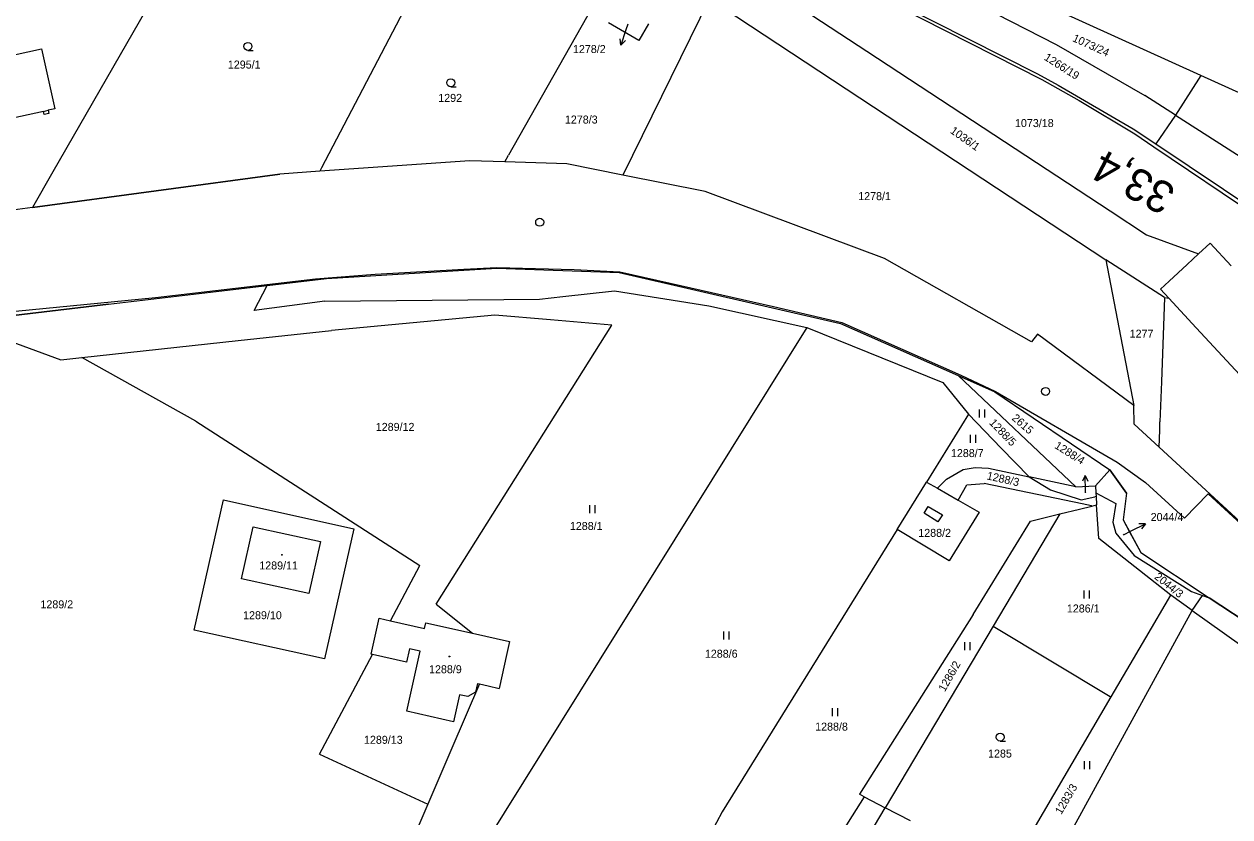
# Model space of a CAD drawing. Extents: x -805011 to -803920, y -1150790 to -1150234.
# Drawn here: x -804429.5 to -804203.4, y -1150584.2 to -1150435.6 of the extents above; entities that cross this region are included whole.
import ezdxf

# ---------------------------------------------------------------- set-up
doc = ezdxf.new("R2010")
doc.units = 0
for name, color, linetype in [('Default', 7, 'Continuous'), ('kilometráž - vrstava 7', 7, 'Continuous'), ('kn_celek - Cisla parcel pomocna', 7, 'Continuous'), ('kn_celek - Cisla pozemkovych parcel', 7, 'Continuous'), ('kn_celek - Cisla stavebnich parcel', 7, 'Continuous'), ('kn_celek - Hranice parcel', 7, 'Continuous'), ('kn_celek - Vnitrni kresby', 7, 'Continuous'), ('kn_celek - Znacky budov', 7, 'Continuous'), ('kn_celek - Znacky kultur', 7, 'Continuous'), ('plochy - SZDC', 7, 'Continuous'), ('PSR_C2_2_trasa_Vimperk - Kabelová trasa', 7, 'Continuous')]:
    doc.layers.add(name, color=color, linetype=linetype)

# ---------------------------------------------------------------- blocks, each defined once
blk = doc.blocks.new('306')
at = {"layer": 'Default'}
for p, q in [((-5.2, 0), (-5.2, 15)), ((4.8, 0), (4.8, 15))]:
    blk.add_line(p, q, dxfattribs=at)
blk = doc.blocks.new('304')
at = {"layer": 'Default'}
blk.add_line((-0.1, 0), (9.9, 0), dxfattribs=at)
blk.add_circle((-0.1, 7.5), 7.5, dxfattribs=at)
blk = doc.blocks.new('402')
at = {"layer": 'Default'}
for p, q in [((-0.8, 0.8), (0.7, 0.8)), ((-0.8, 0.8), (-0.8, -0.7)), ((0.7, 0.8), (0.7, -0.7)), ((0.7, -0.7), (-0.8, -0.7))]:
    blk.add_line(p, q, dxfattribs=at)
blk = doc.blocks.new('Z61')
at = {"layer": 'Default'}
for p, q in [((0, 0), (30, 0)), ((30, 0), (19.2, 5.3)), ((30, 0), (19.2, -5.3))]:
    blk.add_line(p, q, dxfattribs=at)

msp = doc.modelspace()

# ---------------------------------------------------------------- linework, layer by layer
at = {"layer": 'kilometráž - vrstava 7'}
for centre in [(-804332.82, -1150472.71), (-804237.98, -1150504.43)]:
    msp.add_circle(centre, 0.75, dxfattribs=at)
at = {"layer": 'kn_celek - Cisla parcel pomocna'}
for p, q in [((-804316.32, -1150435.58), (-804316.66, -1150436.63)), ((-804230.51, -1150523.46), (-804230.52, -1150523.18)), ((-804223.38, -1150531.32), (-804221.96, -1150530.6))]:
    msp.add_line(p, q, dxfattribs=at)
at = {"layer": 'kn_celek - Hranice parcel'}
for p, q in [((-804385.7, -1150396.46), (-804424.05, -1150463.28)), ((-804298.67, -1150422.8), (-804271.5, -1150440.64)), ((-804208.87, -1150445.2), (-804247.42, -1150427.68)), ((-804321.6, -1150429.95), (-804338.65, -1150460.11)), ((-804357.62, -1150431.72), (-804373.69, -1150462.54)), ((-804301, -1150430.74), (-804317.22, -1150463.88)), ((-804301, -1150430.74), (-804226.72, -1150479.76)), ((-804265.66, -1150432.25), (-804238.71, -1150445.94)), ((-804265.36, -1150431.82), (-804239.5, -1150444.89)), ((-804250.04, -1150432.2), (-804236.02, -1150439.39)), ((-804314.22, -1150438.61), (-804319.91, -1150435.33)), ((-804312.41, -1150435.5), (-804314.22, -1150438.61)), ((-804236.02, -1150439.39), (-804219.37, -1150448.94)), ((-804498.86, -1150456.4), (-804426.19, -1150440.19)), ((-804426.19, -1150440.19), (-804423.68, -1150451.44)), ((-804271.5, -1150440.64), (-804225.88, -1150470.58)), ((-804239.5, -1150444.89), (-804235.62, -1150446.99)), ((-804238.71, -1150445.94), (-804231.71, -1150449.89)), ((-804208.87, -1150445.2), (-804213.63, -1150452.62)), ((-804163.83, -1150465.67), (-804208.87, -1150445.2)), ((-804235.62, -1150446.99), (-804221.57, -1150455.2)), ((-804231.71, -1150449.89), (-804221.27, -1150456.12)), ((-804213.63, -1150452.62), (-804219.37, -1150448.94)), ((-804425.85, -1150451.92), (-804476.67, -1150463.25)), ((-804425.72, -1150452.51), (-804425.85, -1150451.92)), ((-804424.84, -1150452.31), (-804425.72, -1150452.51)), ((-804423.68, -1150451.44), (-804424.97, -1150451.73)), ((-804424.97, -1150451.73), (-804424.84, -1150452.31)), ((-804213.63, -1150452.62), (-804217.33, -1150458.04)), ((-804213.63, -1150452.62), (-804176.02, -1150476.77)), ((-804221.57, -1150455.2), (-804217.33, -1150458.04)), ((-804221.27, -1150456.12), (-804217.68, -1150458.55)), ((-804217.68, -1150458.55), (-804183.31, -1150481.83)), ((-804217.33, -1150458.04), (-804188.61, -1150477.27)), ((-804345.91, -1150461.18), (-804374.01, -1150463.14)), ((-804339.38, -1150461.4), (-804345.91, -1150461.18)), ((-804339.38, -1150461.4), (-804338.65, -1150460.11)), ((-804327.71, -1150461.78), (-804339.38, -1150461.4)), ((-804317.22, -1150463.88), (-804327.71, -1150461.78)), ((-804424.05, -1150463.28), (-804427.86, -1150469.92)), ((-804427.86, -1150469.92), (-804381.52, -1150463.67)), ((-804374.01, -1150463.14), (-804381.52, -1150463.67)), ((-804373.69, -1150462.54), (-804374.01, -1150463.14)), ((-804301.77, -1150466.98), (-804317.22, -1150463.88)), ((-804268.19, -1150479.5), (-804301.77, -1150466.98)), ((-804427.86, -1150469.92), (-804473.24, -1150476.04)), ((-804225.88, -1150470.58), (-804219.07, -1150475.05)), ((-804219.07, -1150475.05), (-804209.3, -1150478.65)), ((-804207.15, -1150476.64), (-804209.3, -1150478.65)), ((-804207.15, -1150476.64), (-804203.22, -1150480.89)), ((-804240.65, -1150495.11), (-804268.19, -1150479.5)), ((-804215.71, -1150486.85), (-804226.72, -1150479.76)), ((-804226.72, -1150479.76), (-804221.47, -1150507.06)), ((-804209.3, -1150478.65), (-804211.42, -1150480.62)), ((-804372.75, -1150483.24), (-804340.86, -1150481.33)), ((-804340.86, -1150481.33), (-804317.89, -1150482.17)), ((-804317.89, -1150482.17), (-804276.4, -1150491.69)), ((-804211.42, -1150480.62), (-804214.82, -1150483.78)), ((-804413.66, -1150488.07), (-804383.87, -1150484.55)), ((-804386.34, -1150489.27), (-804383.87, -1150484.55)), ((-804383.87, -1150484.55), (-804372.75, -1150483.24)), ((-804214.82, -1150483.78), (-804216.44, -1150485.29)), ((-804332.85, -1150487.17), (-804328.48, -1150486.67)), ((-804328.48, -1150486.67), (-804318.77, -1150485.56)), ((-804318.77, -1150485.56), (-804301.09, -1150488.42)), ((-804216.44, -1150485.29), (-804214.9, -1150486.96)), ((-804215.71, -1150486.85), (-804216.27, -1150502.62)), ((-804215.71, -1150486.85), (-804214.9, -1150486.96)), ((-804214.9, -1150486.96), (-804209.74, -1150492.54)), ((-804413.66, -1150488.07), (-804432.51, -1150490.32)), ((-804373.12, -1150487.5), (-804386.34, -1150489.27)), ((-804373.12, -1150487.5), (-804332.85, -1150487.17)), ((-804301.09, -1150488.42), (-804282.73, -1150492.43)), ((-804341.25, -1150490.12), (-804371.82, -1150493.04)), ((-804330.8, -1150491.03), (-804341.25, -1150490.12)), ((-804319.3, -1150492.03), (-804330.8, -1150491.03)), ((-804436.85, -1150493.24), (-804422.59, -1150498.49)), ((-804389.32, -1150494.92), (-804371.82, -1150493.04)), ((-804352.2, -1150544.3), (-804319.3, -1150492.03)), ((-804282.73, -1150492.43), (-804344.13, -1150590.85)), ((-804282.73, -1150492.43), (-804257.22, -1150502.78)), ((-804276.4, -1150491.69), (-804254.35, -1150501.48)), ((-804239.52, -1150493.68), (-804240.65, -1150495.11)), ((-804221.47, -1150507.06), (-804239.52, -1150493.68)), ((-804209.74, -1150492.54), (-804206.45, -1150496.09)), ((-804418.66, -1150498.07), (-804389.32, -1150494.92)), ((-804422.59, -1150498.49), (-804418.66, -1150498.07)), ((-804397.29, -1150510.02), (-804418.66, -1150498.07)), ((-804206.45, -1150496.09), (-804175.77, -1150529.26)), ((-804257.22, -1150502.78), (-804252.42, -1150508.72)), ((-804254.35, -1150501.48), (-804247.48, -1150504.53)), ((-804232.31, -1150522.31), (-804254.35, -1150501.48)), ((-804216.27, -1150502.62), (-804216.54, -1150510.11)), ((-804247.48, -1150504.53), (-804225.97, -1150519.11)), ((-804221.41, -1150510.55), (-804221.47, -1150507.06)), ((-804252.42, -1150508.72), (-804260.3, -1150521.44)), ((-804252.42, -1150508.72), (-804246.34, -1150515.05)), ((-804397.29, -1150510.02), (-804355.28, -1150537.09)), ((-804221.41, -1150510.55), (-804216.71, -1150514.88)), ((-804216.71, -1150514.88), (-804216.6, -1150511.73)), ((-804216.6, -1150511.73), (-804216.54, -1150510.11)), ((-804241.05, -1150520.43), (-804246.34, -1150515.05)), ((-804216.71, -1150514.88), (-804196.65, -1150533.37)), ((-804258.26, -1150522.6), (-804256.57, -1150520.87)), ((-804256.57, -1150520.87), (-804253.42, -1150519.06)), ((-804253.42, -1150519.06), (-804251.17, -1150518.68)), ((-804251.17, -1150518.68), (-804248.68, -1150518.8)), ((-804248.68, -1150518.8), (-804241.05, -1150520.43)), ((-804241.05, -1150520.43), (-804237.05, -1150522.86)), ((-804232.31, -1150522.31), (-804241.05, -1150520.43)), ((-804228.6, -1150522.11), (-804225.97, -1150519.11)), ((-804222.81, -1150523.51), (-804225.97, -1150519.11)), ((-804265.8, -1150530.32), (-804260.3, -1150521.44)), ((-804260.3, -1150521.44), (-804258.26, -1150522.6)), ((-804258.26, -1150522.6), (-804254.38, -1150524.81)), ((-804254.38, -1150524.81), (-804252.74, -1150521.97)), ((-804252.74, -1150521.97), (-804249.49, -1150521.69)), ((-804231.13, -1150525.52), (-804249.49, -1150521.69)), ((-804237.05, -1150522.86), (-804231.31, -1150524.77)), ((-804232.31, -1150522.31), (-804228.6, -1150522.11)), ((-804228.6, -1150522.11), (-804228.54, -1150523.48)), ((-804397.61, -1150549.18), (-804392.08, -1150524.79)), ((-804392.08, -1150524.79), (-804367.66, -1150530.19)), ((-804254.38, -1150524.81), (-804250.43, -1150527.06)), ((-804231.31, -1150524.77), (-804228.73, -1150524.18)), ((-804228.51, -1150524.13), (-804228.73, -1150524.18)), ((-804228.54, -1150523.48), (-804228.51, -1150524.13)), ((-804228.54, -1150523.48), (-804224.81, -1150525.46)), ((-804228.51, -1150524.13), (-804228.45, -1150525.73)), ((-804222.81, -1150523.51), (-804223.47, -1150528.51)), ((-804250.43, -1150527.06), (-804256.08, -1150536.2)), ((-804235.33, -1150527.4), (-804247.84, -1150548.47)), ((-804240.82, -1150528.74), (-804235.33, -1150527.4)), ((-804235.33, -1150527.4), (-804231.62, -1150526.5)), ((-804231.62, -1150526.5), (-804229.32, -1150525.94)), ((-804229.39, -1150525.88), (-804231.13, -1150525.52)), ((-804229.39, -1150525.88), (-804229.32, -1150525.94)), ((-804229.32, -1150525.94), (-804228.45, -1150525.73)), ((-804228.03, -1150531.99), (-804228.45, -1150525.73)), ((-804224.81, -1150525.46), (-804225.36, -1150528.93)), ((-804388.69, -1150539.57), (-804386.51, -1150529.81)), ((-804386.51, -1150529.81), (-804373.89, -1150532.57)), ((-804251.57, -1150546.24), (-804240.82, -1150528.74)), ((-804225.36, -1150528.93), (-804224.83, -1150531.01)), ((-804223.47, -1150528.51), (-804220.13, -1150534.61)), ((-804367.66, -1150530.19), (-804373.16, -1150554.57)), ((-804265.8, -1150530.32), (-804298.61, -1150583.27)), ((-804256.08, -1150536.2), (-804265.8, -1150530.32)), ((-804214.51, -1150542.63), (-804228.03, -1150531.99)), ((-804224.83, -1150531.01), (-804221.38, -1150535.19)), ((-804373.89, -1150532.57), (-804376.12, -1150542.34)), ((-804221.38, -1150535.19), (-804210.61, -1150541.96)), ((-804220.13, -1150534.61), (-804207.3, -1150543.14)), ((-804360.79, -1150547.46), (-804355.28, -1150537.09)), ((-804376.12, -1150542.34), (-804388.69, -1150539.57)), ((-804219.19, -1150550.65), (-804214.51, -1150542.63)), ((-804210.52, -1150545.49), (-804214.51, -1150542.63)), ((-804210.61, -1150541.96), (-804208.56, -1150542.69)), ((-804210.52, -1150545.49), (-804208.56, -1150542.69)), ((-804208.56, -1150542.69), (-804207.3, -1150543.14)), ((-804196.79, -1150550.13), (-804207.3, -1150543.14)), ((-804352.2, -1150544.3), (-804345.42, -1150549.78)), ((-804237.26, -1150594.36), (-804210.52, -1150545.49)), ((-804210.52, -1150545.49), (-804197.78, -1150554.62)), ((-804364.41, -1150553.72), (-804362.93, -1150546.98)), ((-804362.93, -1150546.98), (-804360.79, -1150547.46)), ((-804360.79, -1150547.46), (-804354.4, -1150548.88)), ((-804354.4, -1150548.88), (-804354.17, -1150547.83)), ((-804354.17, -1150547.83), (-804345.42, -1150549.78)), ((-804251.57, -1150546.24), (-804272.88, -1150579.95)), ((-804373.16, -1150554.57), (-804397.61, -1150549.18)), ((-804345.42, -1150549.78), (-804338.45, -1150551.33)), ((-804247.84, -1150548.47), (-804268.04, -1150582.49)), ((-804247.84, -1150548.47), (-804225.88, -1150561.63)), ((-804338.45, -1150551.33), (-804338.96, -1150553.59)), ((-804225.71, -1150561.73), (-804219.19, -1150550.65)), ((-804374.09, -1150572.48), (-804364.15, -1150553.78)), ((-804364.15, -1150553.78), (-804364.41, -1150553.72)), ((-804357.78, -1150555.19), (-804364.15, -1150553.78)), ((-804357.21, -1150552.7), (-804357.78, -1150555.19)), ((-804357.73, -1150564.42), (-804355.25, -1150553.13)), ((-804355.25, -1150553.13), (-804357.21, -1150552.7)), ((-804338.96, -1150553.59), (-804340.43, -1150560.12)), ((-804344.07, -1150559.29), (-804349.26, -1150571.32)), ((-804344.48, -1150559.2), (-804344.87, -1150560.8)), ((-804344.48, -1150559.2), (-804344.07, -1150559.29)), ((-804344.07, -1150559.29), (-804342.48, -1150559.65)), ((-804347.82, -1150561.33), (-804348.99, -1150566.39)), ((-804346.3, -1150561.65), (-804347.82, -1150561.33)), ((-804344.87, -1150560.8), (-804346.3, -1150561.65)), ((-804342.48, -1150559.65), (-804340.43, -1150560.12)), ((-804244.16, -1150593.22), (-804225.71, -1150561.73)), ((-804225.88, -1150561.63), (-804225.71, -1150561.73)), ((-804348.99, -1150566.39), (-804357.73, -1150564.42)), ((-804374.09, -1150572.48), (-804353.79, -1150581.83)), ((-804349.26, -1150571.32), (-804353.79, -1150581.83)), ((-804353.79, -1150581.83), (-804355.87, -1150586.66)), ((-804271.97, -1150580.46), (-804281.49, -1150595.48)), ((-804271.97, -1150580.46), (-804272.88, -1150579.95)), ((-804271.97, -1150580.46), (-804268.04, -1150582.49)), ((-804298.61, -1150583.27), (-804317.72, -1150619.16)), ((-804272.21, -1150589.52), (-804268.04, -1150582.49)), ((-804263.3, -1150584.93), (-804268.04, -1150582.49))]:
    msp.add_line(p, q, dxfattribs=at)
at = {"layer": 'kn_celek - Vnitrni kresby'}
for p, q in [((-804425.85, -1150451.92), (-804424.97, -1150451.73)), ((-804260.76, -1150527.29), (-804259.98, -1150526.02)), ((-804258.17, -1150528.89), (-804260.76, -1150527.29)), ((-804259.98, -1150526.02), (-804257.34, -1150527.57)), ((-804257.34, -1150527.57), (-804258.17, -1150528.89))]:
    msp.add_line(p, q, dxfattribs=at)
at = {"layer": 'plochy - SZDC'}
for p, q in [((-804345.91, -1150461.18), (-804374.01, -1150463.14)), ((-804339.38, -1150461.4), (-804345.91, -1150461.18)), ((-804327.71, -1150461.78), (-804339.38, -1150461.4)), ((-804317.22, -1150463.88), (-804327.71, -1150461.78)), ((-804381.52, -1150463.67), (-804427.86, -1150469.92)), ((-804374.01, -1150463.14), (-804381.52, -1150463.67)), ((-804301.77, -1150466.98), (-804317.22, -1150463.88)), ((-804268.19, -1150479.5), (-804301.77, -1150466.98)), ((-804427.86, -1150469.92), (-804473.24, -1150476.04)), ((-804240.65, -1150495.11), (-804268.19, -1150479.5)), ((-804372.75, -1150483.24), (-804340.86, -1150481.33)), ((-804340.86, -1150481.33), (-804317.89, -1150482.17)), ((-804317.89, -1150482.17), (-804276.4, -1150491.69)), ((-804413.66, -1150488.07), (-804383.87, -1150484.55)), ((-804383.87, -1150484.55), (-804372.75, -1150483.24)), ((-804432.51, -1150490.32), (-804413.66, -1150488.07)), ((-804276.4, -1150491.69), (-804254.35, -1150501.48)), ((-804239.52, -1150493.68), (-804240.65, -1150495.11)), ((-804221.47, -1150507.06), (-804239.52, -1150493.68)), ((-804254.35, -1150501.48), (-804247.48, -1150504.53)), ((-804247.48, -1150504.53), (-804225.97, -1150519.11)), ((-804221.41, -1150510.55), (-804221.47, -1150507.06)), ((-804216.71, -1150514.88), (-804221.41, -1150510.55)), ((-804196.65, -1150533.37), (-804216.71, -1150514.88)), ((-804225.97, -1150519.11), (-804222.81, -1150523.51)), ((-804222.81, -1150523.51), (-804223.47, -1150528.51)), ((-804220.13, -1150534.61), (-804207.3, -1150543.14)), ((-804207.3, -1150543.14), (-804196.79, -1150550.13))]:
    msp.add_line(p, q, dxfattribs=at)
msp.add_lwpolyline([(-804223.47, -1150528.51), (-804222.25, -1150530.75), (-804220.13, -1150534.61)], dxfattribs=at)
at = {"layer": 'PSR_C2_2_trasa_Vimperk - Kabelová trasa'}
for points in [[(-804529.08, -1150496.27), (-804528.3, -1150496.2), (-804516.01, -1150498.69), (-804469.46, -1150493.33), (-804431.1, -1150489.42), (-804404.84, -1150486.85), (-804374.84, -1150483.32), (-804363.68, -1150482.47), (-804347.01, -1150481.54), (-804340.82, -1150481.2), (-804326.33, -1150481.6), (-804317.79, -1150482), (-804308.33, -1150484.14), (-804289, -1150488.51)], [(-804289, -1150488.51), (-804276.21, -1150491.51), (-804253.89, -1150501.39), (-804247.39, -1150504.47), (-804224.59, -1150517.68), (-804219.24, -1150521.52), (-804211.94, -1150528.21)], [(-804211.94, -1150528.21), (-804207.53, -1150523.61), (-804196.77, -1150533.52), (-804182.83, -1150549.06), (-804177, -1150556.4), (-804170.6, -1150565.5), (-804165.46, -1150573.1), (-804159.32, -1150583.6), (-804148.34, -1150601.45), (-804139.82, -1150616.03), (-804133.21, -1150627.36), (-804121.85, -1150646.68), (-804112.03, -1150660.85), (-804099.51, -1150673.08)]]:
    msp.add_lwpolyline(points, dxfattribs=at)

# ---------------------------------------------------------------- block references
at = {"layer": 'kn_celek - Cisla parcel pomocna'}
for p, xscale, yscale, rotation in [((-804316.66, -1150436.63), 0.10000000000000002, 0.10000000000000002, -107.86158), ((-804230.52, -1150523.18), 0.09999999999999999, 0.10000000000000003, 91.39716000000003), ((-804221.96, -1150530.6), 0.09999999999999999, 0.1, 26.955810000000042)]:
    msp.add_blockref('Z61', p, dxfattribs=dict(at, xscale=xscale, yscale=yscale, rotation=rotation))
at = {"layer": 'kn_celek - Znacky budov', "xscale": 0.1, "yscale": 0.10000000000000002}
for p in [(-804381.13, -1150535.08), (-804349.76, -1150554.14)]:
    msp.add_blockref('402', p, dxfattribs=at)
at = {"layer": 'kn_celek - Znacky kultur', "xscale": 0.1, "yscale": 0.10000000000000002}
for name, p in [('304', (-804387.49, -1150440.49)), ('304', (-804349.47, -1150447.31)), ('306', (-804249.87, -1150509.3)), ('306', (-804251.55, -1150514.07)), ('306', (-804322.9, -1150527.26)), ('306', (-804230.22, -1150543.29)), ('306', (-804297.79, -1150550.97)), ('306', (-804252.61, -1150552.94)), ('306', (-804277.39, -1150565.36)), ('304', (-804246.49, -1150570.01)), ('306', (-804230.16, -1150575.27))]:
    msp.add_blockref(name, p, dxfattribs=at)

# ---------------------------------------------------------------- texts
at = {"layer": 'kilometráž - vrstava 7'}
msp.add_text('33,4', height=6, rotation=152.1809, dxfattribs=at).set_placement((-804213.24, -1150466.23))
at = {"layer": 'kn_celek - Cisla parcel pomocna'}
for s, p in [('1278/2', (-804326.58, -1150440.99)), ('2044/4', (-804218.29, -1150528.74))]:
    msp.add_text(s, height=1.5, dxfattribs=at).set_placement(p)
msp.add_text('1288/4', height=1.5, rotation=327.8652, dxfattribs=at).set_placement((-804236.44, -1150514.97))
at = {"layer": 'kn_celek - Cisla pozemkovych parcel'}
for s, height, rotation, p in [('1073/24', 1.5, 335.6961, (-804233.08, -1150438.72)), ('1266/19', 1.5, 327.4692, (-804238.39, -1150442.16)), ('1036/1', 1.5, 324.9, (-804256, -1150455.87)), ('2615', 1.5, 318.8825, (-804244.43, -1150509.63)), ('1288/5', 1.5, 314.1, (-804248.65, -1150510.43)), ('1288/3', 1.5, 347.4, (-804249.1, -1150520.91)), ('2044/4', 0.1, 303.3, (-804223.57, -1150531.11)), ('2044/3', 1.5, 321.3, (-804217.71, -1150539.43)), ('1286/2', 1.5, 60.3, (-804256.88, -1150560.86)), ('1283/3', 1.5, 59.739, (-804235.04, -1150583.88))]:
    msp.add_text(s, height=height, rotation=rotation, dxfattribs=at).set_placement(p)
for s, height, p in [('1295/1', 1.5, (-804391.27, -1150443.9)), ('1292', 1.5, (-804351.83, -1150450.15)), ('1278/3', 1.5, (-804328.09, -1150454.21)), ('1073/18', 1.5, (-804243.72, -1150454.87)), ('1278/1', 1.5, (-804273.11, -1150468.57)), ('1277', 1.5, (-804222.23, -1150494.36)), ('1289/12', 1.5, (-804363.54, -1150511.84)), ('1288/7', 1.5, (-804255.73, -1150516.75)), ('1288/4', 0.1, (-804230.78, -1150523.51)), ('1288/1', 1.5, (-804327.16, -1150530.42)), ('1288/2', 1.5, (-804261.85, -1150531.71)), ('1289/2', 1.5, (-804426.4, -1150545.11)), ('1289/10', 1.5, (-804388.41, -1150547.15)), ('1286/1', 1.5, (-804234, -1150545.89)), ('1288/6', 1.5, (-804301.85, -1150554.37)), ('1288/8', 1.5, (-804281.18, -1150568.04)), ('1289/13', 1.5, (-804365.75, -1150570.51)), ('1285', 1.5, (-804248.77, -1150573.09))]:
    msp.add_text(s, height=height, dxfattribs=at).set_placement(p)
at = {"layer": 'kn_celek - Cisla stavebnich parcel'}
for s, p in [('1289/11', (-804385.38, -1150537.82)), ('1288/9', (-804353.56, -1150557.28))]:
    msp.add_text(s, height=1.5, dxfattribs=at).set_placement(p)

doc.saveas('drawing.dxf')
